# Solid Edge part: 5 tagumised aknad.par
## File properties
Author: Henri
Template: Normal.par
Last saved by: Henri
Revision: 21
Application: Solid Edge
Accuracy: 0,990
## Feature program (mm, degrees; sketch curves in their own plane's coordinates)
sketch for "unnamed Protrusion 1" #1 plane through (-212.5, -250, 42.4987) normal (-1, 0, 0) x-axis (0, -1, 0)
  line (109.7295, 32.5013) -> (224.7295, 32.5013)
  arc centre (224.7295, 27.5013) radius 5 from (224.7295, 32.5013) to (229.7295, 27.5013) cw
  line (229.7295, 27.5013) -> (229.7295, 22.5013)
  arc centre (224.7295, 22.5013) radius 5 from (229.7295, 22.5013) to (224.7295, 17.5013) cw
  line (224.7295, 17.5013) -> (109.7295, 17.5013)
  arc centre (109.7295, 22.5013) radius 5 from (104.7295, 22.5013) to (109.7295, 17.5013) ccw
  line (104.7295, 27.5013) -> (104.7295, 22.5013)
  arc centre (109.7295, 27.5013) radius 5 from (104.7295, 27.5013) to (109.7295, 32.5013) cw
sketch for "unnamed Protrusion 1" #2 plane through (-212.5, -250, 42.4987) normal (-1, 0, 0) x-axis (0, -1, 0)
  line (-224.7295, 32.5013) -> (-109.7295, 32.5013)
  arc centre (-109.7295, 27.5013) radius 5 from (-109.7295, 32.5013) to (-104.7295, 27.5013) cw
  line (-104.7295, 27.5013) -> (-104.7295, 22.5013)
  arc centre (-109.7295, 22.5013) radius 5 from (-109.7295, 17.5013) to (-104.7295, 22.5013) ccw
  line (-109.7295, 17.5013) -> (-224.7295, 17.5013)
  arc centre (-224.7295, 22.5013) radius 5 from (-229.7295, 22.5013) to (-224.7295, 17.5013) ccw
  line (-229.7295, 27.5013) -> (-229.7295, 22.5013)
  arc centre (-224.7295, 27.5013) radius 5 from (-229.7295, 27.5013) to (-224.7295, 32.5013) cw
extrude "unnamed Protrusion 1" add finite 5 along -normal
sketch for "unnamed Protrusion 2" #1 plane through (-212.5, -82.7705, 67.5) normal (-1, 0, 0) x-axis (0, -1, 0)
  line (-57.5, 9) -> (57.5, 9)
  arc centre (57.5, 2.5) radius 6.5 from (57.5, 9) to (64, 2.5) cw
  line (64, 2.5) -> (64, -2.5)
  arc centre (57.5, -2.5) radius 6.5 from (57.5, -9) to (64, -2.5) ccw
  line (57.5, -9) -> (-57.5, -9)
  arc centre (-57.5, -2.5) radius 6.5 from (-64, -2.5) to (-57.5, -9) ccw
  line (-64, 2.5) -> (-64, -2.5)
  arc centre (-57.5, 2.5) radius 6.5 from (-64, 2.5) to (-57.5, 9) cw
sketch for "unnamed Protrusion 2" #2 plane through (-212.5, -82.7705, 67.5) normal (-1, 0, 0) x-axis (0, -1, 0)
  line (-57.5, 6) -> (57.5, 6)
  arc centre (57.5, 2.5) radius 3.5 from (57.5, 6) to (61, 2.5) cw
  line (61, 2.5) -> (61, -2.5)
  arc centre (57.5, -2.5) radius 3.5 from (57.5, -6) to (61, -2.5) ccw
  line (57.5, -6) -> (-57.5, -6)
  arc centre (-57.5, -2.5) radius 3.5 from (-61, -2.5) to (-57.5, -6) ccw
  line (-61, 2.5) -> (-61, -2.5)
  arc centre (-57.5, 2.5) radius 3.5 from (-61, 2.5) to (-57.5, 6) cw
sketch for "unnamed Protrusion 2" #3 plane through (-212.5, -82.7705, 67.5) normal (-1, 0, 0) x-axis (0, -1, 0)
  line (276.9591, 9) -> (391.9591, 9)
  arc centre (391.9591, 2.5) radius 6.5 from (391.9591, 9) to (398.4591, 2.5) cw
  line (398.4591, 2.5) -> (398.4591, -2.5)
  arc centre (391.9591, -2.5) radius 6.5 from (398.4591, -2.5) to (391.9591, -9) cw
  line (391.9591, -9) -> (276.9591, -9)
  arc centre (276.9591, -2.5) radius 6.5 from (270.4591, -2.5) to (276.9591, -9) ccw
  line (270.4591, 2.5) -> (270.4591, -2.5)
  arc centre (276.9591, 2.5) radius 6.5 from (270.4591, 2.5) to (276.9591, 9) cw
sketch for "unnamed Protrusion 2" #4 plane through (-212.5, -82.7705, 67.5) normal (-1, 0, 0) x-axis (0, -1, 0)
  line (276.9591, 6) -> (391.9591, 6)
  arc centre (391.9591, 2.5) radius 3.5 from (391.9591, 6) to (395.4591, 2.5) cw
  line (395.4591, 2.5) -> (395.4591, -2.5)
  arc centre (391.9591, -2.5) radius 3.5 from (395.4591, -2.5) to (391.9591, -6) cw
  line (391.9591, -6) -> (276.9591, -6)
  arc centre (276.9591, -2.5) radius 3.5 from (273.4591, -2.5) to (276.9591, -6) ccw
  line (273.4591, 2.5) -> (273.4591, -2.5)
  arc centre (276.9591, 2.5) radius 3.5 from (273.4591, 2.5) to (276.9591, 6) cw
extrude "unnamed Protrusion 2" add finite 1.5 along +normal
fillet "Round_20" radius 0.5
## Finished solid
Body 1: solid body, 88 faces, 208 edges, 128 vertices, 2 separate solids.
  Faces by surface: cylinder 40, plane 32, torus 16
  Edges by curve: line 112, circle 96
Bounding box of the edges (mm; curved faces can reach further): 6.500 x 462.459 x 18.000, from (-214, -481.2295, 58.5) to (-207.5, -18.7705, 76.5).
Cylindrical faces by radius (mm): R0.5 x16, R3.5 x8, R5 x8, R6.5 x8
Toroidal faces (ring radius, tube radius in mm): R4 r0.5 x8, R6 r0.5 x8
Planar faces by outward normal: +x 4, +y 6, +z 6, -x 4, -y 6, -z 6
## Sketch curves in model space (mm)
line (-212.5, -25.2705, 76.5) -> (-212.5, -140.2705, 76.5)
arc centre (-212.5, -140.2705, 70) radius 6.5 from (-212.5, -140.2705, 76.5) through (-212.5, -144.9984, 74.4606) to (-212.5, -146.7705, 70)
line (-212.5, -146.7705, 70) -> (-212.5, -146.7705, 65)
arc centre (-212.5, -140.2705, 65) radius 6.5 from (-212.5, -140.2705, 58.5) through (-212.5, -144.9984, 60.5394) to (-212.5, -146.7705, 65)
line (-212.5, -140.2705, 58.5) -> (-212.5, -25.2705, 58.5)
arc centre (-212.5, -25.2705, 65) radius 6.5 from (-212.5, -18.7705, 65) through (-212.5, -20.8099, 60.2721) to (-212.5, -25.2705, 58.5)
line (-212.5, -18.7705, 70) -> (-212.5, -18.7705, 65)
arc centre (-212.5, -25.2705, 70) radius 6.5 from (-212.5, -18.7705, 70) through (-212.5, -20.8099, 74.7279) to (-212.5, -25.2705, 76.5)
arc centre (-212.5, -140.2705, 70) radius 3.5 from (-212.5, -140.2705, 73.5) through (-212.5, -142.8163, 72.4018) to (-212.5, -143.7705, 70)
line (-212.5, -143.7705, 70) -> (-212.5, -143.7705, 65)
arc centre (-212.5, -140.2705, 65) radius 3.5 from (-212.5, -140.2705, 61.5) through (-212.5, -142.8163, 62.5982) to (-212.5, -143.7705, 65)
line (-212.5, -140.2705, 61.5) -> (-212.5, -25.2705, 61.5)
arc centre (-212.5, -25.2705, 65) radius 3.5 from (-212.5, -21.7705, 65) through (-212.5, -22.8686, 62.4542) to (-212.5, -25.2705, 61.5)
line (-212.5, -21.7705, 70) -> (-212.5, -21.7705, 65)
arc centre (-212.5, -25.2705, 70) radius 3.5 from (-212.5, -21.7705, 70) through (-212.5, -22.8686, 72.5458) to (-212.5, -25.2705, 73.5)
line (-212.5, -25.2705, 73.5) -> (-212.5, -140.2705, 73.5)
line (-212.5, -359.7295, 76.5) -> (-212.5, -474.7295, 76.5)
arc centre (-212.5, -474.7295, 70) radius 6.5 from (-212.5, -474.7295, 76.5) through (-212.5, -479.4575, 74.4606) to (-212.5, -481.2295, 70)
line (-212.5, -481.2295, 70) -> (-212.5, -481.2295, 65)
arc centre (-212.5, -474.7295, 65) radius 6.5 from (-212.5, -481.2295, 65) through (-212.5, -479.1901, 60.2721) to (-212.5, -474.7295, 58.5)
line (-212.5, -474.7295, 58.5) -> (-212.5, -359.7295, 58.5)
arc centre (-212.5, -359.7295, 65) radius 6.5 from (-212.5, -353.2295, 65) through (-212.5, -355.269, 60.2721) to (-212.5, -359.7295, 58.5)
line (-212.5, -353.2295, 70) -> (-212.5, -353.2295, 65)
arc centre (-212.5, -359.7295, 70) radius 6.5 from (-212.5, -353.2295, 70) through (-212.5, -355.269, 74.7279) to (-212.5, -359.7295, 76.5)
arc centre (-212.5, -474.7295, 70) radius 3.5 from (-212.5, -474.7295, 73.5) through (-212.5, -477.2753, 72.4018) to (-212.5, -478.2295, 70)
line (-212.5, -478.2295, 70) -> (-212.5, -478.2295, 65)
arc centre (-212.5, -474.7295, 65) radius 3.5 from (-212.5, -478.2295, 65) through (-212.5, -477.1314, 62.4542) to (-212.5, -474.7295, 61.5)
line (-212.5, -474.7295, 61.5) -> (-212.5, -359.7295, 61.5)
arc centre (-212.5, -359.7295, 65) radius 3.5 from (-212.5, -356.2295, 65) through (-212.5, -357.3277, 62.4542) to (-212.5, -359.7295, 61.5)
line (-212.5, -356.2295, 70) -> (-212.5, -356.2295, 65)
arc centre (-212.5, -359.7295, 70) radius 3.5 from (-212.5, -356.2295, 70) through (-212.5, -357.3277, 72.5458) to (-212.5, -359.7295, 73.5)
line (-212.5, -359.7295, 73.5) -> (-212.5, -474.7295, 73.5)
arc centre (-212.5, -140.2705, 70) radius 5 from (-212.5, -140.2705, 75) through (-212.5, -143.9073, 73.4312) to (-212.5, -145.2705, 70)
line (-212.5, -145.2705, 70) -> (-212.5, -145.2705, 65)
arc centre (-212.5, -140.2705, 65) radius 5 from (-212.5, -140.2705, 60) through (-212.5, -143.9073, 61.5688) to (-212.5, -145.2705, 65)
line (-212.5, -140.2705, 60) -> (-212.5, -25.2705, 60)
arc centre (-212.5, -25.2705, 65) radius 5 from (-212.5, -20.2705, 65) through (-212.5, -21.8393, 61.3631) to (-212.5, -25.2705, 60)
line (-212.5, -20.2705, 70) -> (-212.5, -20.2705, 65)
arc centre (-212.5, -25.2705, 70) radius 5 from (-212.5, -20.2705, 70) through (-212.5, -21.8393, 73.6369) to (-212.5, -25.2705, 75)
line (-212.5, -25.2705, 75) -> (-212.5, -140.2705, 75)
arc centre (-212.5, -474.7295, 70) radius 5 from (-212.5, -474.7295, 75) through (-212.5, -478.3664, 73.4312) to (-212.5, -479.7295, 70)
line (-212.5, -479.7295, 70) -> (-212.5, -479.7295, 65)
arc centre (-212.5, -474.7295, 65) radius 5 from (-212.5, -479.7295, 65) through (-212.5, -478.1607, 61.3631) to (-212.5, -474.7295, 60)
line (-212.5, -474.7295, 60) -> (-212.5, -359.7295, 60)
arc centre (-212.5, -359.7295, 65) radius 5 from (-212.5, -354.7295, 65) through (-212.5, -356.2983, 61.3631) to (-212.5, -359.7295, 60)
line (-212.5, -354.7295, 70) -> (-212.5, -354.7295, 65)
arc centre (-212.5, -359.7295, 70) radius 5 from (-212.5, -354.7295, 70) through (-212.5, -356.2983, 73.6369) to (-212.5, -359.7295, 75)
line (-212.5, -359.7295, 75) -> (-212.5, -474.7295, 75)
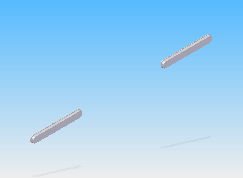
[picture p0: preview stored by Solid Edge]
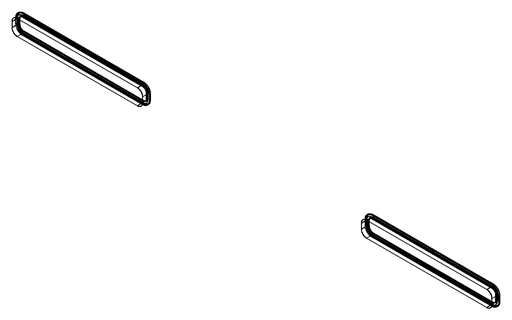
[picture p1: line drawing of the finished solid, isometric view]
